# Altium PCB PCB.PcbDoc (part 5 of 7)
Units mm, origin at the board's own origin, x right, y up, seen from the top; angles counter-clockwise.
Board outline 243.2 x 142.8 mm, 4 copper layers (Top Layer, Layer 1, Layer 2, Bottom Layer), stack 0.603 mm thick; 451 components, 380 nets, 2276 pads, 1520 vias.
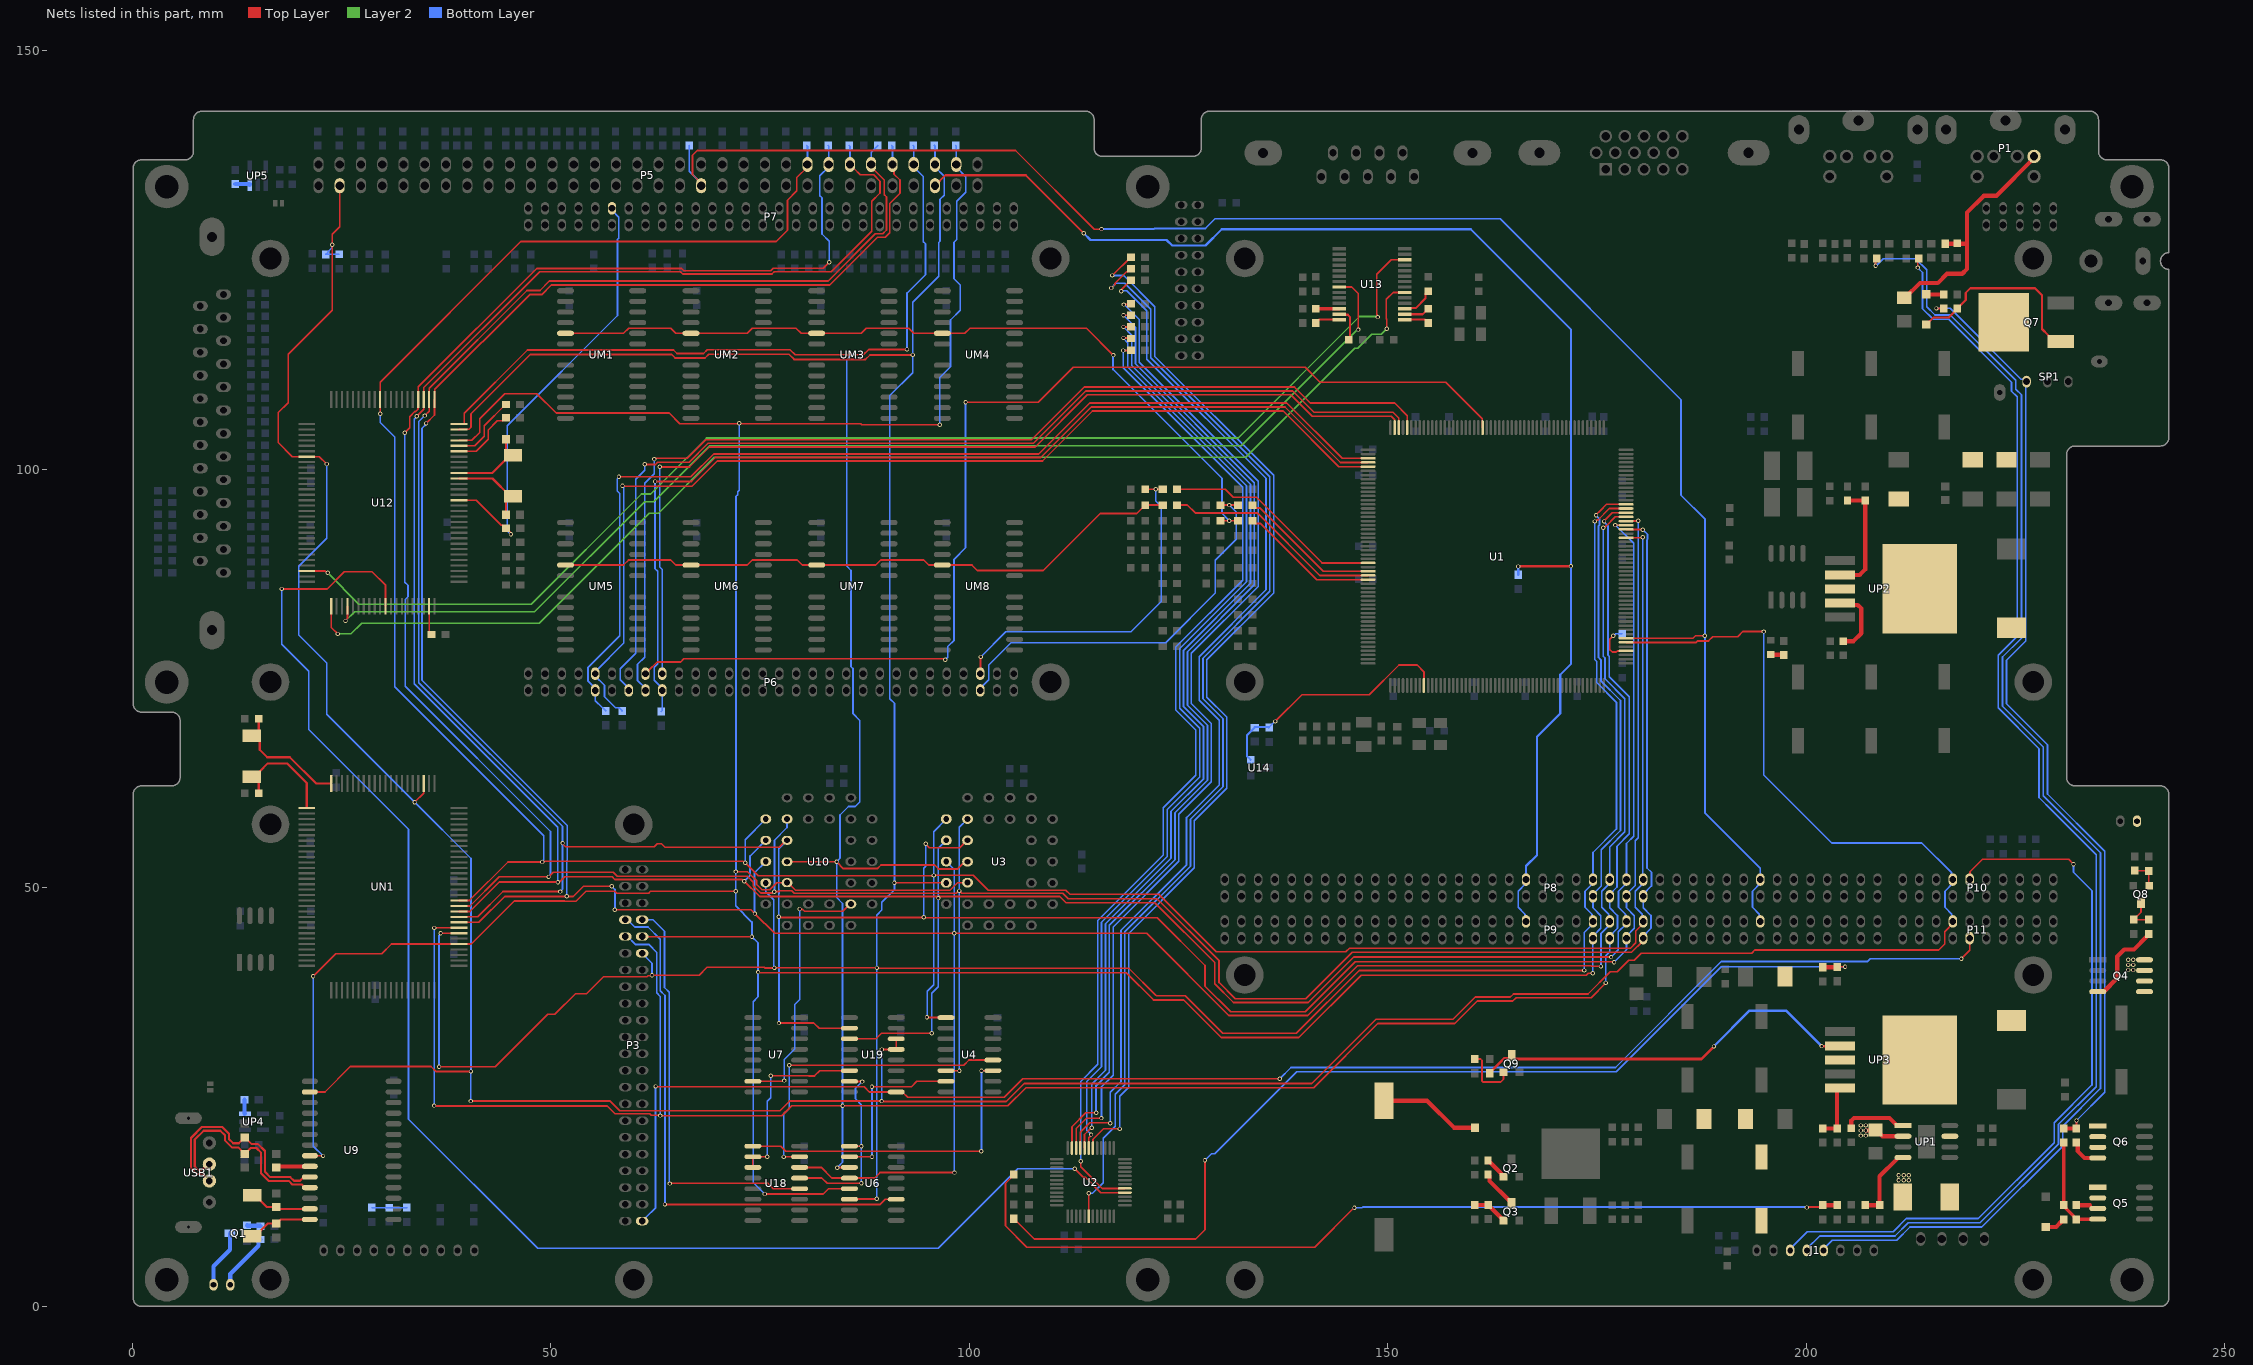
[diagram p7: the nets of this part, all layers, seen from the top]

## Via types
v1: diameter 0.508, hole 0.305, Top Layer to Bottom Layer, tented both sides, 1451 vias
v2: diameter 0.508, hole 0.3, Top Layer to Bottom Layer, 67 vias
v3: diameter 1.2, hole 1.2, Top Layer to Bottom Layer, 2 vias

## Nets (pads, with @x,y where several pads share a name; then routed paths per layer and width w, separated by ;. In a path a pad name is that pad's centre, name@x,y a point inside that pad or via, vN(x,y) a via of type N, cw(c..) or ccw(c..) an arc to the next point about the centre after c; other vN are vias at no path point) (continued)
NERROR#: P6.9 R83.1 U1.55 | length 126.6
  Top Layer w0.203: v1(58.126,99.126) 66.724,99.126 69.447,101.849 108.301,101.849 114.4,107.948 137.93,107.948 144.542,101.336 U1.55@147.647,101.336
  Bottom Layer w0.203: R83.1@56.552,71.136 56.552,71.174 56.209,71.517 56.171,71.517 55.3,72.387 P6.9@55.3,73.6 55.3,73.85 54.443,74.707 54.443,76.368 58.228,80.153 58.228,97.12 57.923,97.425 57.923,98.855 58.126,99.058 v1(58.126,99.126)
NetBAT1_1: BAT1.1 D1.A | length 12.2
  Top Layer w0.508: BAT1.1@149.53,24.585 154.663,24.585 157.886,21.361 D1.A@160.401,21.361
NetC10_1: C10.1 U9.9 | length 4.1
  Top Layer w0.508: C10.1@17.2,16.583 17.333,16.716 21.176,16.716 U9.9@21.2,16.74
NetC11_2: C11.2 U9.13 X4.1 | length 7.6
  Top Layer w0.254: X4.1@14.3,13.3 14.65,13.3 16.084,11.866 C11.2@17.206,11.866 17.412,11.66 U9.13@21.2,11.66
NetC12_2: C12.2 U9.14 X4.2 | length 7.7
  Top Layer w0.254: X4.2@14.3,8.4 14.65,8.4 16.15,9.9 C12.2@17.2,9.9 17.238,9.9 17.728,10.39 U9.14@21.2,10.39
NetC13_1: C13.1 U9.10 USB1.D+ | length 26.4
  Top Layer w0.254: USB1.D+@9.2,15 8.386,15.814 7.733,15.814 6.996,16.551 6.996,20.132 8.317,21.453 10.705,21.453 11.543,20.615 11.543,19.996 12.044,19.495 12.714,19.495 C13.1@13.419,20.2 ; C13.1@13.4,20.2 C13.1@13.419,20.2 ; U9.10@21.2,15.47 20.466,15.47 20.023,15.027 19.301,15.027 18.87,15.459 16.457,15.459 15.835,16.08 15.835,18.569 14.983,19.421 14.217,19.421 13.438,20.2 C13.1@13.419,20.2
NetC14_1: C14.1 U9.11 USB1.D- | length 24.9
  Top Layer w0.254: USB1.D-@9.2,17 8.995,17 8.266,16.272 7.922,16.272 7.453,16.74 7.453,19.943 8.506,20.996 10.515,20.996 11.086,20.426 11.086,19.806 11.88,19.012 12.647,19.012 C14.1@13.425,18.233 ; C14.1@13.406,18.233 C14.1@13.425,18.233 ; U9.11@21.2,14.2 20.598,14.2 20.228,14.57 19.112,14.57 18.68,15.002 16.267,15.002 15.378,15.891 15.378,18.38 14.819,18.939 14.15,18.939 13.444,18.233 C14.1@13.425,18.233
NetC17_1: C17.1 P1.4 R95.1 RP4.1 | length 29.2
  Top Layer w0.508: RP4.1@211.695,120.513 211.783,120.513 213.561,122.291 215.708,122.291 216.8,123.383 218.629,123.383 219.188,123.942 219.188,127.016 ; R95.1@216.572,126.965 218.045,126.965 219.137,126.965 219.188,127.016 ; P1.4@227.2,137.4 227.2,137.2 222.7,132.7 221.2,132.7 219.188,130.688 219.188,127.016
NetC22_2: C22.2 UP2.4 | length 8.3
  Top Layer w0.508: UP2.4@204.024,84.064 204.283,83.805 206.138,83.805 206.564,83.378 206.564,80.432 205.622,79.49 C22.2@204.38,79.49
NetC117_2: C117.2 U12.21 X5.2 | length 9.6
  Top Layer w0.254: U12.21@39.026,99.579 43.009,99.579 44.504,101.074 44.504,101.094 X5.2@45.118,101.708 ; C117.2@44.649,103.6 44.649,102.34 45.273,101.717 X5.2@45.477,101.717 ; X5.2@45.477,101.708 X5.2@45.749,101.708
NetC118_2: C118.2 U12.20 X5.1 | length 9.8
  Top Layer w0.254: U12.20@39.026,98.929 43.016,98.929 45.127,96.817 X5.1@45.273,96.817 ; C118.2@44.649,94.605 44.649,96.194 X5.1@45.273,96.817 ; X5.1@45.477,96.817 X5.1@45.273,96.817
NetC123_2: C123.2 U13.13 | length 4.2
  Top Layer w0.254: U13.13@144.2,118.55 144.273,118.477 145.202,118.477 145.452,118.227 145.452,115.652 C123.2@145.3,115.5
NetC124_1: C124.1 U13.12 | length 2.8
  Top Layer w0.381: C124.1@141.4,119.2 U13.12@144.2,119.2
NetC124_2: C124.2 U13.14 | length 3
  Top Layer w0.254: C124.2@141.4,117.5 141.8,117.9 U13.14@144.2,117.9
NetC125_1: C125.1 U13.16 | length 3.1
  Top Layer w0.254: U13.16@152,118.55 154.15,118.55 C125.1@154.8,119.2
NetC125_2: C125.2 U13.15 | length 3
  Top Layer w0.254: U13.15@152,117.9 154.4,117.9 C125.2@154.8,117.5
NetC126_1: C126.1 U13.17 | length 4
  Top Layer w0.254: U13.17@152,119.2 152.073,119.273 153.33,119.273 154.477,120.42 154.477,120.977 C126.1@154.8,121.3
NetCN1_1: CN1.1 UN1.51 X6.2 | length 13.4
  Top Layer w0.254: X6.2@14.251,63.292 14.601,63.292 15.224,63.915 15.224,63.92 16.191,64.887 18.477,64.887 20.826,62.539 UN1.51@20.826,59.55 ; X6.2@14.477,63.292 15.1,62.669 CN1.1@15.1,61.3
NetCN2_1: CN2.1 UN1.50 X6.1 | length 14.7
  Top Layer w0.254: X6.1@14.251,68.192 14.594,68.192 15.1,68.698 CN2.1@15.1,70.2 ; X6.1@14.563,68.192 14.601,68.192 15.224,67.569 15.224,66.515 16.115,65.624 18.807,65.624 21.956,62.475 UN1.50@23.751,62.475
NetCN5_1: CN5.1 RN3.1 RN4.1 | length 4.2
  Bottom Layer w0.203: RN3.1@28.6,11.8 RN4.1@32.8,11.8
NetCP1_2: CP1.2 UP1.1 | length 7.6
  Top Layer w0.508: CP1.2@205.37,21.301 205.37,22.215 205.675,22.52 209.917,22.52 210.831,21.606 UP1.1@211.542,21.606
NetCP7_1: CP7.1 DP7.A LP2.1 UP3.0 UP3.3
NetCP7_2: CP7.2 DP8.A DP9.K
NetDP1_K: DP1.K R104.1 | length 2.5
  Top Layer w0.508: DP1.K@228.6,9.5 229.839,9.5 230.516,10.177 230.554,10.177 230.745,10.368 R104.1@230.745,10.406
NetDP2_A: DP2.A Q7.1 R105.2 | length 23.3
  Top Layer w0.254: DP2.A@214.336,117.313 215.2,118.176 217.04,118.176 218.045,119.182 R105.2@218.045,119.22 218.045,119.258 219.035,120.248 219.035,121.097 219.594,121.656 227.316,121.656 228.154,120.818 228.154,116.779 228.909,116.024 228.909,115.965 229.238,115.636 Q7.1@230.389,115.636
NetDP2_K: DP2.K R107.1 | length 2.1
  Top Layer w0.508: DP2.K@214.336,120.913 214.34,120.916 216.416,120.916 R107.1@216.419,120.92
NetDP3_A: DP3.A DP4.A Q7.3
NetDP6_K: DP6.K LP1.2 UP2.0 UP2.3
NetJ1_4: J1.4 R19.2 | length 159.9
  Top Layer w0.203: v1(208.266,124.349) 208.266,125.087 R19.2@208.393,125.214
  Bottom Layer w0.203: J1.4@202.063,6.696 202.063,6.896 203.082,7.915 210.795,7.915 212.37,9.49 220.955,9.49 230.618,19.153 230.618,21.529 235.139,26.051 235.139,54.194 229.729,59.604 228.306,61.026 228.306,66.85 223.43,71.727 223.43,77.587 225.69,79.848 225.69,108.922 225.019,109.594 225.019,110.642 217.205,118.456 215.36,118.456 214.387,119.428 214.387,123.841 213.041,125.187 209.18,125.187 208.342,124.349 v1(208.266,124.349)
NetJ1_5: J1.5 R20.2 | length 155
  Top Layer w0.203: v1(213.295,124.12) 213.295,125.087 R20.2@213.422,125.214
  Bottom Layer w0.203: J1.5@200.063,6.696 200.063,6.896 201.59,8.423 210.584,8.423 212.159,9.998 220.744,9.998 230.11,19.363 230.11,21.74 234.631,26.261 234.631,53.983 229.37,59.245 227.798,60.816 227.798,66.64 222.922,71.517 222.922,77.798 225.182,80.058 225.182,108.675 224.511,109.346 224.511,110.431 216.995,117.948 215.149,117.948 213.879,119.218 213.879,123.536 v1(213.295,124.12)
NetL1_1: L1.1 RP3.1 UP1.2 | length 4.8
  Top Layer w0.508: v1(207.097,21.021) 208.164,21.021 RP3.1@208.24,21.098 208.328,21.098 209.09,20.336 UP1.2@211.542,20.336
  other v1: 211.009,15.078 211.619,15.078 212.228,15.078 211.009,15.687 211.619,15.687 212.228,15.687 206.488,20.412 207.097,20.412 206.488,21.021 206.488,21.631 207.097,21.631
NetL1_2: L1.2 UP1.7
NetLED2_1: LED2.1 R92.2 | length 1.6
  Top Layer w0.508: LED2.1@195.744,77.892 195.781,77.855 197.281,77.855 R92.2@197.318,77.818
NetLS1_1: LS1.1 Q1.C | length 6.9
  Bottom Layer w0.508: LS1.1@9.7,2.6 9.7,4.802 11.668,6.77 Q1.C@11.668,8.735
NetLS1_2: LS1.2 R3.1 | length 6.9
  Bottom Layer w0.508: LS1.2@11.7,2.6 11.7,3.877 15.071,7.248 15.071,7.809 15.262,8 R3.1@15.3,8
NetPP2_2: PP2.2 Q4.5 Q4.6 Q4.7 Q4.8
  other v1: 238.441,40.198 239.051,40.198 238.441,40.808 239.051,40.808 238.441,41.418 239.051,41.418
NetQ1_B: Q1.B R4.2 | length 1.6
  Bottom Layer w0.508: Q1.B@13.7,9.7 13.75,9.65 15.25,9.65 R4.2@15.3,9.6
NetQ2_B: Q2.B R6.2 | length 2.7
  Top Layer w0.508: R6.2@161.962,17.464 161.962,17.425 162.152,17.235 162.19,17.235 163.6,15.825 163.6,15.713 Q2.B@163.803,15.51
NetQ3_B: Q3.B R5.1 R7.2 | length 4.2
  Top Layer w0.508: R5.1@160.387,12.106 160.399,12.118 162.001,12.118 R7.2@162.012,12.13 162.012,12.091 163.6,10.504 163.6,10.48 Q3.B@163.803,10.277
NetQ3_C: Q3.C R6.1 | length 4.7
  Top Layer w0.508: R6.1@161.962,15.764 162.152,15.573 162.152,14.989 164.451,12.69 164.565,12.69 164.768,12.487 Q3.C@164.768,12.309
NetQ4_4: Q4.4 R101.1 | length 10.5
  Top Layer w0.508: Q4.4@234.809,37.608 235.52,37.608 237.146,39.233 237.146,41.824 237.984,42.662 239.127,42.662 240.714,44.25 240.714,44.326 R101.1@240.905,44.516
NetQ5_1: Q5.1 Q5.2 Q5.3 Q6.1 Q6.2 Q6.3 RP6.1 | length 1.7
  Top Layer w0.508: RP6.1@232.218,12.106 233.844,12.106 233.869,12.081
NetQ5_4: Q5.4 R104.2 R106.1 RP6.2 | length 12.4
  Top Layer w0.381: R106.1@230.745,19.574 R104.2@230.745,12.106 230.999,11.852 230.999,11.725 231.964,10.76 231.964,10.66 RP6.2@232.218,10.406 232.23,10.418 234.797,10.418 Q5.4@234.809,10.43
NetQ6_4: Q6.4 R108.1 | length 3.8
  Top Layer w0.508: R108.1@232.218,19.574 232.408,19.383 232.408,18.57 233.234,17.745 Q6.4@234.809,17.745
NetQ8_B: Q8.B R102.2 R103.1 | length 3.5
  Top Layer w0.203: R102.2@239.228,52.062 240.878,52.062 R103.1@240.905,52.035 240.905,50.295 Q8.B@240.943,50.257
NetQ8_C: Q8.C R100.2 R101.2 | length 4.1
  Top Layer w0.203: Q8.C@239.978,48.225 239.978,47.105 239.127,46.254 R100.2@239.127,46.216 R101.2@240.905,46.216
NetQ9_B: Q9.B R119.2 | length 7
  Top Layer w0.203: R119.2@160.376,29.564 161.063,29.564 161.239,29.388 161.239,26.941 161.358,26.822 163.5,26.822 163.817,27.14 Q9.B@163.817,27.965
NetQ9_C: Q9.C R118.1 UP3.2 | length 47.2
  Top Layer w0.203: R118.1@162.154,27.864 R118.1@162.154,27.902 ; Q9.C@164.452,29.667 Q9.C@164.782,29.997
  Top Layer w0.305: R118.1@162.154,27.902 163.919,29.667 Q9.C@164.452,29.667 ; Q9.C@164.782,29.997 164.782,29.87 165.087,29.566 187.452,29.566 v2(188.951,31.064) ; v2(201.813,31.105) UP3.2@204.024,31.105
  Bottom Layer w0.305: v2(188.951,31.064) 188.951,31.09 193.218,35.357 197.561,35.357 v2(201.813,31.105)
NetR8_2: R8.2 U2.43 | length 114
  Top Layer w0.203: U2.43@114.256,18.928 114.256,20.171 114.54,20.455 v1(114.54,20.537) ; v1(118.412,115.713) 119.213,115.713 R8.2@119.287,115.638
  Bottom Layer w0.203: v1(114.54,20.537) 114.021,21.057 114.021,26.873 115.792,28.644 115.792,45.914 123.63,53.753 123.63,59.372 127.515,63.257 127.515,69.073 125.127,71.46 125.127,78.603 133.114,86.59 133.114,98.054 118.931,112.237 118.931,115.119 118.412,115.638 v1(118.412,115.713)
NetR9_2: R9.2 U2.47 | length 118.6
  Top Layer w0.203: U2.47@112.256,18.928 112.256,21.476 113.919,23.139 v1(115.164,23.139) ; v1(118.412,118.413) R9.2@119.287,118.413
  Bottom Layer w0.203: v1(115.164,23.139) 115.138,23.165 115.138,26.391 116.72,27.972 116.72,45.53 124.558,53.368 124.558,58.988 128.443,62.873 128.443,69.457 126.055,71.845 126.055,78.219 134.042,86.205 134.042,98.41 119.839,112.613 119.839,116.986 v1(118.412,118.413)
NetR11_2: R11.2 U2.18 | length 135.1
  Top Layer w0.203: U2.18@114.256,10.778 114.265,10.787 114.265,13.504 v1(114.275,13.513) ; v1(116.951,121.682) 116.969,121.682 117.394,122.106 117.394,122.25 118.776,123.632 118.956,123.632 R11.2@119.299,123.974
  Bottom Layer w0.203: v1(114.275,13.513) 114.706,13.513 115.976,14.783 115.976,20.091 117.424,21.539 117.424,25.349 118.576,26.501 118.576,44.761 126.415,52.599 126.415,58.219 130.299,62.104 130.299,70.226 127.912,72.614 127.912,77.45 135.899,85.436 135.899,99.122 121.655,113.366 121.655,119.138 118.549,122.244 117.46,122.244 117.286,122.071 117.286,122.022 116.951,121.686 v1(116.951,121.682)
NetR12_2: R12.2 U2.29 | length 120.7
  Top Layer w0.203: v1(113.297,17.335) 113.297,16.672 115.866,14.103 U2.29@118.581,14.103 ; v1(118.372,114.214) 119.251,114.214 R12.2@119.299,114.262
  Bottom Layer w0.203: v1(113.297,17.335) 113.297,26.886 115.337,28.927 115.337,46.116 123.166,53.945 123.166,59.565 127.051,63.449 127.051,68.88 124.663,71.268 124.663,78.795 132.65,86.782 132.65,97.876 118.372,112.154 v1(118.372,114.214)
NetR13_2: R13.2 U2.44 | length 115.5
  Top Layer w0.203: U2.44@113.756,18.928 113.756,20.544 114.574,21.361 v1(114.605,21.361) ; v1(118.412,117.026) R13.2@119.287,117.026
  Bottom Layer w0.203: v1(114.605,21.361) 114.605,26.568 116.256,28.219 116.256,45.722 124.094,53.561 124.094,59.18 127.979,63.065 127.979,69.265 125.591,71.652 125.591,78.411 133.578,86.398 133.578,98.232 119.385,112.425 119.385,116.053 v1(118.412,117.026)
NetR14_2: R14.2 U2.46 | length 120.4
  Top Layer w0.203: U2.46@112.756,18.928 112.756,21.265 113.995,22.504 v1(115.773,22.504) ; v1(118.434,119.7) 119.187,119.7 R14.2@119.299,119.812
  Bottom Layer w0.203: v1(115.773,22.504) 115.773,26.213 117.184,27.624 117.184,45.338 125.022,53.176 125.022,58.796 128.907,62.68 128.907,69.649 126.52,72.037 126.52,78.026 134.506,86.013 134.506,98.588 120.293,112.801 120.293,117.92 118.512,119.7 v1(118.434,119.7)
NetR15_2: R15.2 U2.45 | length 124.4
  Top Layer w0.203: U2.45@113.256,18.928 113.256,20.803 114.399,21.946 v1@116.84,21.946 ; v1(118.136,121.299) 118.194,121.357 118.194,121.52 119.238,122.564 R15.2@119.276,122.564
  Bottom Layer w0.203: v1(116.84,21.895) 116.84,25.603 118.112,26.875 118.112,44.953 125.951,52.792 125.951,58.411 129.835,62.296 129.835,70.034 127.448,72.421 127.448,77.642 135.435,85.629 135.435,98.944 121.201,113.177 121.201,118.957 118.796,121.363 118.593,121.363 118.574,121.344 118.181,121.344 v1(118.136,121.299)
NetR16_2: R16.2 U2.42 | length 128.2
  Top Layer w0.203: U2.42@114.756,18.928 114.775,18.946 114.775,19.982 116.027,21.234 117.932,21.234 v1(117.958,21.209) ; v1@117.08,123.181 119.261,125.362 R16.2@119.299,125.362
  Bottom Layer w0.203: v1(117.08,123.18) 118.426,123.18 122.16,119.446 122.16,113.503 136.363,99.3 136.363,85.244 128.376,77.257 128.376,72.806 130.763,70.418 130.763,61.911 126.879,58.027 126.879,52.407 119.04,44.569 119.04,26.187 117.958,25.105 v1(117.958,21.209)
NetR88_2: R88.2 R89.1 R90.2 | length 121.4
  Top Layer w0.203: R90.2@105.321,10.476 105.321,10.438 105.664,10.095 105.702,10.095 107.745,8.052 127.025,8.052 128.143,9.169 v1(128.143,17.475) ; R89.1@203.662,40.554 203.697,40.589 v1(204.622,40.589)
  Top Layer w0.508: R88.2@201.967,40.527 201.98,40.54 203.648,40.54 R89.1@203.662,40.554
  Bottom Layer w0.203: v1(128.143,17.475) 128.93,18.263 129.311,18.263 139.09,28.042 177.292,28.042 189.84,40.589 v1(204.622,40.589)
NetR94_1: R94.1 U1.160 | length 5.1
  Top Layer w0.203: v1(176.922,80.127) 176.516,79.721 176.516,78.476 176.795,78.197 177.281,78.197 177.401,78.317 178.444,78.317 U1.160@178.463,78.336
  Bottom Layer w0.203: v1(176.922,80.127) 177.005,80.127 177.233,80.356 R94.1@177.989,80.356
NetR96_2: R96.2 R97.1 R99.2 | length 109.1
  Top Layer w0.203: R99.2@105.321,15.776 105.321,15.738 104.318,14.735 104.318,9.627 106.858,7.087 141.249,7.087 145.948,11.786 v1(145.999,11.786) ; v1(200.036,11.827) 200.095,11.885 201.746,11.885 R97.1@201.967,12.106
  Top Layer w0.508: R97.1@201.967,12.106 R96.2@203.662,12.106
  Bottom Layer w0.203: v1(145.999,11.786) 146.914,11.786 147.015,11.887 199.893,11.887 199.954,11.827 v1(200.036,11.827)
NetR106_2: R106.2 R107.2 R108.2 SP1.3 | length 112.7
  Top Layer w0.203: R108.2@232.218,21.274 232.269,21.324 v1(232.269,22.215)
  Top Layer w0.254: v1(215.53,119.243) 216.396,119.243 R107.2@216.419,119.22
  Top Layer w0.508: R106.2@230.745,21.274 R108.2@232.218,21.274
  Bottom Layer w0.203: v1(215.53,119.243) 217.18,119.243 225.644,110.779 226.021,110.779 SP1.3@226.3,110.5 ; SP1.3@226.211,109.981 226.211,79.505 223.912,77.206 223.912,72.025 228.814,67.122 228.814,61.23 235.647,54.397 235.647,25.593 v1(232.269,22.215)
NetR110_1: R110.1 R111.1 UP2.2 | length 13.6
  Top Layer w0.508: UP2.2@204.024,87.392 206.361,87.392 207.021,88.052 R110.1@207.021,96.282 R111.1@204.912,96.282
NetR112_2: R112.2 R113.2 UP1.4 | length 8.9
  Top Layer w0.508: R113.2@207.053,12.106 R112.2@208.748,12.106 208.748,15.56 210.812,17.624 210.812,17.749 210.859,17.796 UP1.4@211.542,17.796
NetR114_2: R114.2 R115.2 UP3.5 | length 6.7
  Top Layer w0.508: R114.2@201.967,21.274 R115.2@203.662,21.274 203.662,25.797 203.941,26.076 UP3.5@204.024,26.076
NetR116_2: R116.2 UP5.3 | length 1.8
  Bottom Layer w0.508: R116.2@12.3,134.1 14.011,134.1 14.032,134.079 UP5.3@14.032,134.017
NetR117_2: R117.2 UP4.3 | length 1.7
  Bottom Layer w0.508: R117.2@13.4,24.7 13.4,23.044 13.421,23.023 UP4.3@13.437,23.023
NetR145_1: R145.1 U12.26 | length 8.3
  Top Layer w0.203: U12.26@39.026,102.829 40.899,102.829 42.023,103.952 42.023,105.206 R145.1@44.577,107.76
NetR146_1: R146.1 U12.25 | length 7.9
  Top Layer w0.203: U12.25@39.026,102.179 41.062,102.179 42.505,103.622 42.505,104.714 43.608,105.817 44.272,105.817 R146.1@44.615,106.16
NetR147_1: R147.1 U12.99 | length 3.4
  Top Layer w0.203: U12.99@35.451,83.654 35.451,80.349 R147.1@35.5,80.3
NetU4_7: U4.7 U6.2 | length 20.3
  Top Layer w0.203: U6.2@85.671,17.882 v1(88.367,17.882) ; v1(88.352,26.254) 93.077,26.254 93.723,26.9 U4.7@97.212,26.9
  Bottom Layer w0.203: v1(88.352,26.254) 88.365,26.241 v1@88.365,17.805
NetU4_11: U4.11 U18.1 | length 38.5
  Top Layer w0.203: U18.1@74.128,19.153 77.469,19.153 78.08,18.542 v1(101.422,18.542) ; v1@101.448,28.169 U4.11@102.799,28.169
  Bottom Layer w0.203: v1(101.422,18.542) 101.435,18.555 101.435,28.156 v1(101.448,28.169)
NetU4_12: U4.12 U18.15 | length 37.7
  Top Layer w0.203: v1(77.822,17.872) 77.827,17.877 79.711,17.877 U18.15@79.716,17.883 ; v1(78.472,28.819) 99.325,28.819 99.946,29.44 U4.12@102.8,29.44
  Bottom Layer w0.203: v1(77.822,17.872) 77.822,23.009 78.472,23.659 v1(78.472,28.819)
NetU6_1: U6.1 U18.13 U19.7 | length 23.4
  Top Layer w0.203: U18.13@79.716,15.343 82.371,15.343 83.007,14.707 v1(87.097,14.707) ; U6.1@85.671,19.152 v1(87.097,19.152) ; U19.7@85.67,26.9 85.684,26.887 87.185,26.887 v1(87.198,26.873)
  Bottom Layer w0.203: v1(87.097,14.707) v1(87.097,19.152) 87.097,24.105 86.385,24.816 86.385,26.06 v1(87.198,26.873)
NetU7_7: U7.7 U10.22 | length 31.6
  Top Layer w0.203: U7.7@74.128,26.9 77.715,26.9 77.805,26.99 v1(77.888,26.99) ; v1(79.716,47.488) 79.775,47.43 80.098,47.43 80.294,47.234 84.883,47.234 85.721,48.072 U10.22@85.838,48.072
  Bottom Layer w0.203: v1(77.888,26.99) 77.888,29.515 79.131,30.758 79.131,36.083 79.716,36.668 v1(79.716,47.488)
NetU18_2: U18.2 U18.3 U19.6 | length 22.5
  Top Layer w0.203: U18.3@74.128,16.613 U18.2@74.128,17.883 v1(75.844,17.882) ; v1(76.276,27.559) 76.286,27.549 80.807,27.549 80.823,27.534 81.483,27.534 82.12,28.17 U19.6@85.67,28.17
  Bottom Layer w0.203: v1(75.844,17.882) 75.844,24.511 76.276,24.943 v1(76.276,27.559)
NM/IO#: P6.13 U1.50 | length 124.9
  Top Layer w0.203: v1@61.2,100.6 62.492,100.6 62.772,100.879 66.536,100.879 68.772,103.114 107.656,103.114 113.919,109.377 138.626,109.377 141.163,106.84 150.612,106.84 151.305,106.147 U1.50@151.305,104.994
  Bottom Layer w0.203: P6.13@59.3,73.6 59.3,73.85 58.279,74.871 58.279,76.19 60.133,78.044 60.133,98.847 61.2,99.914 v1(61.2,100.625)
NPEREQ: P6.10 R26.1 U1.57 | length 125.6
  Top Layer w0.203: v1(58.558,98.06) 58.616,98.002 66.862,98.002 69.867,101.006 108.731,101.006 114.703,106.978 137.485,106.978 144.127,100.336 U1.57@147.647,100.336
  Bottom Layer w0.203: R26.1@58.507,71.136 58.507,71.174 58.164,71.517 57.72,71.517 56.399,72.837 56.399,74.212 55.3,75.311 P6.10@55.3,75.6 55.3,75.85 58.711,79.261 58.711,97.839 58.667,97.882 58.667,97.893 58.558,98.003 v1(58.558,98.06)
NREADY#: P6.16 U1.30 | length 135.5
  Top Layer w0.203: P6.16@61.3,75.6 61.3,75.634 61.668,76.002 61.702,76.002 62.703,77.003 65.518,77.003 65.883,77.368 96.904,77.368 97.022,77.251 v1(97.104,77.251) ; v1(99.543,108.026) 108.225,108.026 112.406,112.207 140.118,112.207 141.896,110.429 156.914,110.429 161.286,106.057 161.286,105.012 U1.30@161.305,104.994
  Bottom Layer w0.203: v1(97.104,77.251) 97.409,77.556 97.409,78.842 98.171,79.604 98.171,89.281 99.543,90.653 v1(99.543,108.026)
NREADYO#: P6.17 R84.1 U1.56 | length 119.9
  Top Layer w0.203: v1(62.452,98.56) 62.459,98.568 66.801,98.568 69.661,101.428 108.516,101.428 114.551,107.463 137.707,107.463 144.335,100.836 U1.56@147.647,100.836
  Bottom Layer w0.203: v1(62.452,98.56) 62.444,98.553 62.444,88.154 62.775,87.823 62.775,76.8 62.343,76.368 62.343,74.807 63.3,73.85 P6.17@63.3,73.6 63.3,71.204 R84.1@63.181,71.085
NW/R#: P6.15 U1.48 | length 125.2
  Top Layer w0.203: v1@62.34,101.336 66.28,101.336 68.486,103.542 107.428,103.542 113.732,109.845 138.83,109.845 140.742,107.934 150.8,107.934 152.305,106.429 U1.48@152.305,104.994
  Bottom Layer w0.203: P6.15@61.3,73.6 61.3,73.85 60.336,74.814 60.336,76.698 61.2,77.562 61.2,98.339 62.34,99.479 v1(62.34,101.237)
OSC: P5.59 P8.43 P9.43 R93.2 | length 166.2
  Top Layer w0.254: P5.59@95.89,133.9 97.134,135.144 106.742,135.144 v1(113.651,128.235) ; v1(165.568,88.408) 165.594,88.433 171.842,88.433 v1(171.868,88.458)
  Bottom Layer w0.203: P9.43@166.384,46.116 166.384,46.865 165.558,47.691 165.558,49.622 P8.43@166.5,50.564
  Bottom Layer w0.254: v1(113.651,128.235) 114.464,127.422 123.557,127.422 124.217,126.762 128.205,126.762 130.135,128.692 159.904,128.692 171.893,116.703 171.893,88.484 v1(171.868,88.458) 171.893,88.433 171.893,76.774 170.585,75.466 170.585,70.844 167.829,68.088 167.829,53.945 166.5,52.616 P8.43@166.5,51 ; R93.2@165.568,87.417 v1(165.568,88.408)
OSD: J1.6 P10.11 | length 87.2
  Top Layer w0.203: P10.11@219.5,51 219.546,51.046 219.546,51.936 221.042,53.432 231.329,53.432 v1(231.913,52.848)
  Bottom Layer w0.203: J1.6@198.063,6.696 198.063,6.896 200.098,8.931 210.374,8.931 211.949,10.506 220.534,10.506 229.602,19.574 229.602,21.95 234.123,26.471 234.123,49.671 231.913,51.881 v1(231.913,52.848)
PIDECS1#: P3.37 U18.12 | length 49.4
  Top Layer w0.203: v1(64.186,14.681) 64.211,14.707 75.946,14.707 76.58,14.073 U18.12@79.716,14.073
  Bottom Layer w0.203: P3.37@60.9,46.2 62.207,46.2 63.576,44.831 63.576,38.1 64.127,37.549 64.127,14.74 v1(64.186,14.681)
PIDECS3#: P3.38 U6.11 | length 64.9
  Top Layer w0.203: v1(63.627,12.192) 89.332,12.192 89.943,12.803 U6.11@91.258,12.803
  Bottom Layer w0.203: P3.38@58.9,46.2 59.15,46.2 60.011,45.339 61.595,45.339 63.068,43.866 63.068,37.719 63.627,37.16 v1(63.627,12.192)
PWG: C1.2 R1.2 U1.113 U14.2 | length 29.8
  Top Layer w0.203: v1(136.55,69.901) 139.741,73.091 147.763,73.091 151.319,76.647 153.503,76.647 154.305,75.846 U1.113@154.305,74.206
  Bottom Layer w0.203: R1.2@135.799,69.149 135.799,69.187 136.512,69.901 v1(136.55,69.901)
  Bottom Layer w0.254: U14.2@133.604,65.303 133.172,65.735 133.172,68.261 134.061,69.149 C1.2@134.099,69.149 ; C1.2@134.099,69.249 135.699,69.249 R1.2@135.799,69.149
RAS0#: CM1.1 RM13.2 UM1.5 UM2.5 UM3.5 UM4.5 | length 96.2
  Top Layer w0.203: UM1.5@51.739,116.27 58.673,116.27 59.282,116.879 64.3,116.879 64.91,116.27 UM2.5@66.747,116.27 73.441,116.27 74.05,116.879 79.286,116.879 79.896,116.27 UM3.5@81.756,116.27 87.081,116.27 87.69,116.879 92.748,116.879 93.358,116.27 UM4.5@96.764,116.27 99.455,116.27 100.064,116.879 113.993,116.879 v1(117.207,113.665) ; CM1.1@130,93.877 RM13.2@132.1,93.875
  Bottom Layer w0.203: v1(117.207,113.665) 117.156,113.614 117.156,111.953 130.175,98.934 130.175,94.751 v2(131.049,93.877)
RAS1#: CM2.1 RM14.2 UM5.5 UM6.5 UM7.5 UM8.5 | length 76.4
  Top Layer w0.203: UM5.5@51.739,88.579 58.673,88.579 59.282,89.189 64.3,89.189 64.91,88.579 UM6.5@66.747,88.579 73.441,88.579 74.05,89.189 79.439,89.189 80.048,88.579 UM7.5@81.756,88.579 88.818,88.579 89.428,89.189 94.552,89.189 95.161,88.579 UM8.5@96.764,88.579 100.301,88.579 100.955,87.925 108.829,87.925 115.646,94.742 119.991,94.742 CM2.1@121,95.751 RM14.2@123.1,95.75
RAS2#: CM3.1 P6.55 RM15.2 | length 48.1
  Top Layer w0.203: CM3.1@130,95.752 v2(131.049,95.752) RM15.2@132.098,95.752
  Bottom Layer w0.203: P6.55@101.3,73.6 101.3,73.85 102.311,74.861 102.311,76.632 104.978,79.299 123.444,79.299 129.385,85.239 129.385,89.151 131.877,91.643 131.877,94.924 v2(131.049,95.752)
RAS3#: CM4.1 P6.56 RM16.2 | length 42.1
  Top Layer w0.203: P6.56@101.323,75.623 101.323,77.574 v2(101.346,77.597) ; CM4.1@121,97.627 RM16.2@123.098,97.627
  Bottom Layer w0.203: v2(101.346,77.597) 104.343,80.594 119.304,80.594 122.936,84.226 122.936,95.555 122.25,96.241 v2(122.25,97.638)
RASJ0: RM13.1 U1.84 | length 16.8
  Top Layer w0.203: RM13.1@133.8,93.875 134.143,93.532 134.79,93.532 141.486,86.836 U1.84@147.647,86.836
RASJ1: RM14.1 U1.83 | length 26.3
  Top Layer w0.203: RM14.1@124.8,95.75 126.044,95.75 126.986,94.808 134.403,94.808 141.875,87.336 U1.83@147.647,87.336
RASJ2: RM15.1 U1.82 | length 17.1
  Top Layer w0.203: RM15.1@133.8,95.75 134.143,95.407 134.693,95.407 142.264,87.836 U1.82@147.647,87.836
RASJ3: RM16.1 U1.80 | length 26.5
  Top Layer w0.203: RM16.1@124.8,97.625 130.57,97.625 131.532,96.663 134.301,96.663 142.128,88.836 U1.80@147.647,88.836
RD#: P7.12 R139.1 U12.16 | length 52.9
  Top Layer w0.203: U12.16@39.026,96.329 41.088,96.329 44.079,93.338 44.26,93.338 44.498,93.1 R139.1@44.498,92.995 ; R139.1@44.641,92.995 44.679,92.995 45.165,92.509 45.165,92.327 v1(45.223,92.268)
  Bottom Layer w0.203: v1(45.223,92.268) 44.802,92.69 44.802,105.24 57.954,118.392 57.954,127.478 58.105,127.629 58.105,130.145 57.3,130.95 P7.12@57.3,131.2
REFSH#: P5.37 P8.15 P9.15 R28.1 U1.163 | length 217.1
  Top Layer w0.203: P5.37@67.95,133.9 67.95,134.2 66.915,135.235 66.915,137.531 67.493,138.11 105.503,138.11 114.921,128.692 115.759,128.692 v1(115.784,128.717) ; U1.163@178.463,79.836 186.461,79.836 186.752,80.127 v1(187.87,80.127)
  Bottom Layer w0.203: R28.1@66.519,138.7 66.519,135.631 67.95,134.2 P5.37@67.95,133.9 ; v1(115.784,128.717) 122.027,128.717 122.095,128.786 128.197,128.786 129.348,129.937 139.546,129.937 163.43,129.937 185.025,108.342 185.025,96.915 187.895,94.045 187.895,80.127 187.895,58.943 194.5,52.338 P8.15@194.5,51 ; P9.15@194.384,46.116 194.384,46.865 193.558,47.691 193.558,49.622 P8.15@194.5,50.564
RESET#: P3.1 P11.12 U19.9 | length 183
  Top Layer w0.203: v1(62.509,26.289) 62.56,26.238 87.427,26.238 88.035,25.63 U19.9@91.258,25.63 91.995,25.63 92.631,24.994 104.165,24.994 106.375,27.203 v1(137.081,27.203) ; v2(218.516,41.554) 219.5,42.538 P11.12@219.5,44
  Bottom Layer w0.203: P3.1@60.9,10.2 60.934,10.2 61.302,10.568 61.302,10.602 62.509,11.809 v1(62.509,26.289) ; v1(137.081,27.203) 137.084,27.203 138.43,28.55 177.19,28.55 189.865,41.224 207.315,41.224 207.645,41.554 v2(218.516,41.554)
RI1#: U12.84 U13.8 | length 144.2
  Top Layer w0.203: v1(25.462,81.905) 25.462,81.988 25.701,82.226 U12.84@25.701,83.654 ; U13.8@144.2,121.8 145.663,121.8 146.442,121.021 146.442,116.754 v1(146.484,116.712)
  Layer 2 w0.203: v1(25.462,81.905) 26.553,82.996 48.039,82.996 61.198,96.155 62.29,96.155 68.97,102.835 132.463,102.835 146.22,116.592 146.281,116.592 146.401,116.712 v1(146.484,116.712)
RSTDRV: C9.1 P5.3 P10.13 P11.13 R61.1 U1.162 U9.2 U12.57 U19.13 U19.14 UN1.33 | length 417.7
  Top Layer w0.203: U9.2@21.2,25.63 23.009,25.63 26.046,28.667 35.673,28.667 36.257,28.083 v1(40.448,28.083) ; v1(23.227,100.65) 23.201,100.65 22.323,101.529 U12.57@20.826,101.529 19.105,101.529 17.41,103.223 17.41,106.797 18.604,107.991 18.604,113.757 23.887,119.04 v1(23.887,126.838) 23.878,126.847 23.878,128.098 24.77,128.991 P5.3@24.77,133.9 ; v1(33.711,60.233) 34.799,61.321 UN1.33@34.801,62.475 UN1.33@34.801,62.475 ; v1(40.411,24.536) 57.074,24.536 58.215,23.395 77.37,23.395 78.511,24.536 v1(89.51,24.536) ; v1@89.51,24.486 104.387,24.486 106.546,26.645 140.912,26.645 148.583,34.315 157.785,34.315 160.442,36.973 164.633,36.973 164.998,37.338 173.909,37.338 176.567,39.995 177.405,39.995 178.776,41.367 179.442,41.367 180.28,42.205 193.458,42.205 193.839,42.586 215.81,42.586 216.521,43.297 216.521,44.771 217.5,45.75 P11.13@217.5,46 ; v1(89.521,30.699) 89.526,30.704 91.253,30.704 U19.13@91.258,30.71 U19.14@91.258,31.98 ; U1.162@178.463,79.336 186.85,79.336 187.031,79.518 188.301,79.518 188.809,80.026 191.781,80.026 192.391,80.635 v1(194.905,80.635)
  Bottom Layer w0.203: v1(23.227,100.65) 23.227,92.218 23.227,91.786 19.874,88.433 19.874,80.229 23.227,76.876 23.227,70.738 33.721,60.243 40.451,53.513 40.451,29.937 40.448,29.934 v1(40.448,28.083) 40.43,28.064 40.43,24.555 v1(40.411,24.536) ; v1(23.887,126.838) 23.829,126.779 23.829,126.467 23.365,126.003 23.365,125.965 R61.1@23.1,125.7 C9.1@24.7,125.7 ; v1(89.51,24.536) 89.515,24.542 89.515,30.693 v1(89.521,30.699) ; v1@194.915,80.635 194.915,63.494 203.03,55.379 213.774,55.379 217.348,51.805 217.348,51.152 P10.13@217.5,51 ; P11.13@217.384,46.116 217.384,46.865 216.558,47.691 216.558,49.622 P10.13@217.5,50.564
RSTNP: P6.18 U1.51 | length 118.4
  Top Layer w0.203: v1@63.003,100.295 66.559,100.295 68.956,102.693 107.871,102.693 114.096,108.918 138.378,108.918 140.956,106.34 150.405,106.34 150.805,105.94 U1.51@150.805,104.994
  Bottom Layer w0.203: v1(63.003,100.32) 63.003,98.799 63.01,98.792 63.01,94.514 63.003,94.506 63.003,88.347 63.3,88.05 P6.18@63.3,75.6
RTS1#: U12.81 U13.20 | length 150.1
  Top Layer w0.203: U12.81@23.751,83.654 23.751,81.127 v1(24.522,80.356) ; v1(149.871,116.805) 149.871,117.956 149.82,118.007 149.82,120.335 150.635,121.15 U13.20@152,121.15
  Layer 2 w0.203: v1(24.522,80.356) 26.12,80.356 27.389,81.624 48.607,81.624 61.766,94.783 62.858,94.783 69.538,101.463 133.031,101.463 146.036,114.468 146.391,114.468 148.068,116.144 149.211,116.144 v1(149.871,116.805)
RTS2#: U2.28 U12.91 | length 183.1
  Top Layer w0.203: v1(17.856,85.725) 23.266,85.725 25.324,87.782 28.626,87.782 30.251,86.158 U12.91@30.251,83.654 ; v1(112.595,16.456) 113.608,15.443 113.868,15.443 115.709,13.603 U2.28@118.581,13.603
  Bottom Layer w0.203: v1(17.856,85.725) 17.856,79.121 21.082,75.895 21.082,68.936 32.995,57.023 32.995,22.377 48.412,6.96 96.266,6.96 105.763,16.456 v1(112.595,16.456)
RXD1: U12.78 U13.26 | length 153.1
  Top Layer w0.203: U12.78@20.826,87.879 23.013,87.879 23.246,87.646 v1(23.328,87.646) ; v1(148.779,118.202) 148.721,118.26 148.721,118.511 148.677,118.555 148.677,123.333 150.395,125.05 U13.26@152,125.05
  Layer 2 w0.203: v1(23.328,87.646) 27.064,83.91 47.66,83.91 60.819,97.069 61.911,97.069 68.591,103.749 132.084,103.749 146.613,118.278 148.508,118.278 148.525,118.26 148.721,118.26 v1(148.779,118.202)
SA0: P3.35 P5.62 P8.36 P9.36 R63.1 U1.195 U3.12 U6.5 U9.8 U10.12 U12.27 UN1.5 | length 492.1
  Top Layer w0.203: U9.8@21.2,18.01 21.213,17.997 22.77,17.997 v1(22.784,17.983) ; v1(21.59,39.446) 24.282,42.139 29.794,42.139 30.956,43.3 UN1.5@39.026,43.3 40.481,43.3 45.618,48.438 51.662,48.438 51.672,48.428 53,48.428 54.191,49.619 57.624,49.619 57.857,49.386 61.679,49.386 61.9,49.606 v1(72.071,49.606) ; U12.27@39.026,103.479 40.559,103.479 41.489,104.41 41.489,106.061 44.487,109.058 48.322,109.058 50.633,106.746 64.146,106.746 65.416,105.476 87.032,105.476 87.16,105.348 v1(96.455,105.348) ; P3.35@60.9,44.2 60.915,44.185 74.001,44.185 v1(74.016,44.171) ; v1(72.071,51.954) 72.08,51.945 73.486,51.945 74.575,50.855 74.575,50.413 75.214,49.774 76.142,49.774 77,50.632 U10.12@78.218,50.632 78.335,50.632 79.231,49.736 97.684,49.736 98.58,50.632 U3.12@99.783,50.632 ; 75.024,39.887 118.737,39.887 122.007,36.617 125.614,36.617 130.1,32.131 139.342,32.131 146.799,39.589 173.705,39.589 173.925,39.809 174.476,39.809 v1(174.484,39.817) ; v1(75.54,13.437) 82.523,13.437 83.16,14.073 U6.5@85.67,14.073 ; v1(174.866,94.528) 174.866,94.579 175.432,95.145 176.123,95.836 U1.195@178.463,95.836
  Bottom Layer w0.203: v1(21.59,39.446) 21.615,39.421 21.615,19.152 v1(22.784,17.983) ; v1(72.503,105.525) 72.503,97.526 72.325,97.348 72.325,96.996 72.114,96.785 72.114,51.997 v1(72.071,51.954) v1(72.071,49.606) 72.071,47.868 74.016,45.923 v1(74.016,44.171) 74.752,43.434 74.752,37.008 74.168,36.424 74.168,14.808 v1(75.54,13.437) ; v1(96.455,105.348) 96.455,110.988 97.739,112.272 97.739,117.856 98.908,119.024 98.908,122.037 98.157,122.788 98.157,127.143 98.495,127.481 98.495,132.028 99.579,133.112 99.579,134.991 98.43,136.14 P5.62@98.43,136.44 98.43,138.63 R63.1@98.36,138.7 ; v1(174.484,39.817) 174.492,39.826 174.492,43.992 P9.36@174.5,44 ; P9.36@174.5,44.25 175.437,45.187 175.437,46.701 174.5,47.638 P8.36@174.5,49 174.5,49.25 175.485,50.235 175.485,54.56 177.784,56.859 177.784,72.402 175.449,74.737 175.449,77.265 175.17,77.544 175.17,93.259 175.271,93.361 175.271,94.123 v1(174.866,94.528)
  other v1: 74.752,39.954
SA1: P3.33 P5.60 P8.35 P9.35 R64.1 U1.194 U3.11 U6.6 U10.11 U12.29 UN1.7 | length 440.2
  Top Layer w0.203: v1(36.638,28.641) 43.348,28.641 49.606,34.9 50.47,34.9 52.934,37.363 54.254,37.363 56.277,39.386 61.474,39.386 61.593,39.505 62.019,39.505 v1(62.078,39.564) 67.707,39.564 68.656,40.513 75.509,40.513 75.576,40.446 v1(76.704,40.446) ; v1(36.816,44.593) 36.819,44.596 39.022,44.596 UN1.7@39.026,44.6 ; U12.29@39.026,104.779 39.054,104.807 40.211,104.807 40.448,105.045 40.448,106.645 47.535,113.731 64.433,113.731 64.84,113.325 68.413,113.325 68.845,113.757 78.445,113.757 79.055,113.147 87.59,113.147 88.124,113.681 v1(93.229,113.681) ; v1@76.704,40.361 76.787,40.361 76.904,40.478 88.918,40.478 v1(88.949,40.446) ; U6.6@85.67,12.803 85.703,12.836 88.904,12.836 v1(88.937,12.868) ; v1@88.949,40.402 119.061,40.402 ; v1(91.045,50.638) 91.07,50.612 U3.11@97.242,50.612 ; 119.061,40.376 122.261,37.176 ; 122.314,37.124 125.793,37.124 130.278,32.639 139.065,32.639 146.574,40.148 v1(173.468,40.148) ; v1(174.712,93.792) 174.795,93.792 174.971,93.969 175.098,93.969 176.465,95.336 U1.194@178.463,95.336
  Bottom Layer w0.203: v1(36.638,28.641) 36.638,44.332 36.816,44.51 v1(36.816,44.593) ; P3.33@60.9,42.2 60.934,42.2 61.302,41.832 61.302,41.798 62.078,41.022 v1(62.078,39.564) ; U10.11@75.678,50.612 75.678,49.544 76.633,48.589 76.633,40.717 76.646,40.704 76.646,40.504 v1(76.704,40.446) ; v1(88.937,12.868) 88.943,12.874 88.943,40.44 v1(88.949,40.446) ; v1@88.937,40.446 88.937,46.752 89.546,47.361 89.546,48.276 91.045,49.774 v1(91.045,50.638) 91.045,72.053 90.495,72.602 90.495,108.838 93.229,111.572 v1(93.229,113.681) 93.229,119.98 96.353,123.104 96.353,127.117 96.495,127.259 96.495,132.288 96.988,132.781 96.988,135.042 95.89,136.14 P5.60@95.89,136.44 95.89,138.63 R64.1@95.82,138.7 ; v1(173.468,40.148) 173.468,44.679 174.5,45.711 P9.35@174.5,46 ; P9.35@174.384,46.116 174.384,46.865 173.558,47.691 173.558,49.622 P8.35@174.5,50.564 ; P8.35@174.5,51 174.5,54.235 177.303,57.039 177.303,72.202 174.954,74.552 174.954,77.06 174.712,77.301 v1(174.712,93.792)
SA2: P3.36 P5.58 P8.34 P9.34 R65.1 U1.193 U3.10 U6.3 U10.10 U12.30 UN1.8 | length 465.6
  Top Layer w0.203: v1(36.043,24.003) 36.093,23.952 56.718,23.952 57.656,23.014 61.822,23.014 61.976,22.86 v1@63.068,22.86 ; v1(36.054,45.228) 36.065,45.239 39.014,45.239 UN1.8@39.026,45.25 ; U12.30@39.026,105.429 39.607,105.429 39.635,105.457 39.635,106.696 47.204,114.265 64.654,114.265 65.061,113.858 68.236,113.858 68.693,114.316 78.572,114.316 79.182,113.706 v1(86.008,113.706) ; v1(63.068,22.809) 63.094,22.784 77.572,22.784 78.765,23.978 v1(84.847,23.978) 104.597,23.978 106.756,26.137 141.122,26.137 148.793,33.807 157.984,33.807 160.676,36.5 164.922,36.5 165.319,36.896 174.281,36.896 v1(176.033,38.649) ; U10.10@78.218,53.132 78.221,53.13 84.133,53.13 v1(84.136,53.127) 84.949,52.314 89.007,52.314 89.439,52.746 95.845,52.746 96.315,52.276 98.607,52.276 99.463,53.132 U3.10@99.783,53.132 ; v1(84.201,16.586) 84.214,16.6 85.657,16.6 U6.3@85.67,16.613 ; v1@86.037,113.706 87.336,113.706 87.971,114.341 v1(92.543,114.341) ; v1(175.83,93.792) 175.83,93.869 176.797,94.836 U1.193@178.463,94.836
  Bottom Layer w0.203: v1(36.043,24.003) 36.048,24.009 36.048,45.222 v1(36.054,45.228) ; P3.36@58.9,44.2 59.15,44.2 60.094,43.256 61.671,43.256 62.636,42.291 62.636,37.465 63.068,37.033 v1(63.068,22.809) ; v1(84.201,16.586) 84.847,17.232 v1(84.847,23.978) 84.847,48.149 84.136,48.86 v1(84.136,53.127) 84.542,53.533 84.542,58.715 85.558,59.731 86.371,59.731 86.905,60.264 86.905,70.006 86.105,70.805 86.105,76.183 85.863,76.425 85.863,87.925 85.33,88.458 85.33,92.052 85.355,92.078 85.355,113.082 85.979,113.706 v1(86.008,113.706) ; v1(92.543,114.341) 92.543,121.072 94.753,123.282 94.753,126.965 94.495,127.223 94.495,134.995 93.35,136.14 P5.58@93.35,136.44 93.35,138.63 R65.1@93.28,138.7 ; v1(175.83,93.792) 175.83,93.716 176.287,93.259 176.287,77.828 176.44,77.675 176.44,75.244 178.843,72.84 178.843,56.47 177.364,54.991 177.364,50.114 176.5,49.25 P8.34@176.5,49 176.5,47.638 177.437,46.701 177.437,45.187 P9.34@176.5,44.25 ; v1(176.033,38.649) 176.033,41.903 176.5,42.37 P9.34@176.5,44
SA3: P5.56 P8.33 P9.33 R66.1 U1.192 U3.9 U6.4 U10.9 U12.31 U18.14 UN1.9 | length 412.1
  Top Layer w0.203: v1(35.089,105.502) 36.101,106.514 U12.31@36.101,108.354 36.129,108.382 36.129,109.565 47.458,120.894 48.906,120.894 50.049,122.037 83.323,122.037 89.013,127.727 89.962,127.727 90.495,128.26 90.495,131.783 91.715,133.003 91.715,134.575 91.001,135.289 91.001,136.249 P5.56@90.81,136.44 ; UN1.9@39.026,45.9 41.4,45.9 44.487,48.987 v1@51.88,48.987 ; v1@51.903,48.987 52.67,48.987 53.899,50.216 v1(57.277,50.216) ; v1(57.633,47.396) 58.315,47.396 58.317,47.395 66.115,47.395 66.116,47.396 73.914,47.396 v1(74.371,46.939) 76.733,44.578 v1(98.197,44.578) 121.184,44.578 130.999,34.763 140.421,34.763 146.365,40.706 174.263,40.706 174.34,40.63 v1@175.398,40.63 ; U18.14@79.716,16.613 82.295,16.613 83.565,15.343 U6.4@85.67,15.343 88.673,15.343 89.332,16.002 v1(98.222,16.002) ; v1(175.728,93.028) 175.811,93.028 176.017,93.234 176.061,93.234 177.164,94.336 U1.192@178.463,94.336
  Bottom Layer w0.203: v1(35.089,105.502) 35.089,105.419 34.606,104.937 34.606,74.819 51.954,57.47 51.954,53.307 51.891,53.244 v1(51.891,48.999) ; v1(57.277,50.216) 57.277,50.188 57.658,49.807 57.658,47.422 v1(57.633,47.396) ; v1(74.371,46.939) 74.332,46.979 74.332,51.806 U10.9@75.678,53.152 ; R66.1@90.74,138.7 90.81,138.63 P5.56@90.81,136.44 ; U3.9@97.242,53.152 98.197,52.198 v1(98.197,44.578) v1@98.197,16.002 ; v1(175.449,40.63) 175.449,44.542 176.5,45.593 P9.33@176.5,46 ; v1(175.728,93.028) 175.728,77.686 175.944,77.47 175.944,74.99 178.314,72.621 178.314,56.703 176.5,54.889 P8.33@176.5,51 ; P9.33@176.384,46.116 176.384,46.865 175.558,47.691 175.558,49.622 P8.33@176.5,50.564
SA4: P5.54 P8.32 P9.32 R67.1 U1.191 U3.8 U10.8 U12.32 U19.2 UN1.10 | length 392.7
  Top Layer w0.203: v1(34.936,106.442) 35.451,106.956 U12.32@35.451,108.354 35.454,108.358 35.454,109.703 47.141,121.389 48.69,121.389 49.821,122.52 83.145,122.52 88.771,128.145 89.633,128.145 90.105,128.617 90.105,132.553 89.826,132.832 89.826,134.584 88.27,136.14 P5.54@88.27,136.44 ; UN1.10@39.026,46.55 41.262,46.55 44.283,49.571 v1(51.116,49.571) v1@51.174,49.629 ; v1(51.395,55.362) 51.395,55.285 51.74,54.94 62.357,54.94 62.687,55.27 63.221,55.27 63.637,54.854 77.263,54.854 78.101,55.692 U10.8@78.218,55.692 ; v1(77.227,46.548) 77.286,46.49 77.481,46.49 77.499,46.472 94.525,46.472 v1(94.55,46.498) 94.608,46.439 94.816,46.439 94.821,46.434 122.452,46.434 128.154,40.732 128.154,38.268 131.228,35.195 140.122,35.195 146.116,41.189 v1@177.018,41.189 ; v1(77.241,33.858) 77.259,33.876 81.418,33.876 82.044,33.25 U19.2@85.67,33.25 ; v1(94.779,55.286) 94.779,55.261 95.223,54.816 98.828,54.816 99.704,55.692 U3.8@99.782,55.692 ; U1.191@178.463,93.836 178.479,93.852 179.903,93.852 v1(179.919,93.869)
  Bottom Layer w0.203: v1(34.936,106.442) 34.225,105.73 34.225,74.534 51.395,57.363 v1(51.395,55.362) 51.395,49.85 v1(51.116,49.571) ; v1(77.241,33.858) 77.263,33.88 77.263,46.513 v1(77.227,46.548) 77.227,49.279 77.256,49.309 77.256,49.772 77.227,49.801 77.227,54.702 U10.8@78.218,55.692 ; P5.54@88.27,136.44 88.27,137.885 89.047,138.662 R67.1@89.047,138.7 ; v1(94.55,46.498) 94.55,52.368 94.779,52.596 v1(94.779,55.286) ; v1(177.018,41.129) 178.5,42.611 P9.32@178.5,44 178.5,44.25 179.437,45.187 179.437,46.701 178.5,47.638 P8.32@178.5,49 178.5,49.25 179.549,50.299 179.549,55.626 179.902,55.98 179.902,93.851 v1(179.919,93.869)
SA5: P5.52 P8.31 P9.31 R68.1 U1.190 U3.7 U10.7 U12.33 U19.3 UN1.11 | length 385.8
  Top Layer w0.203: v1(33.971,106.365) 34.801,107.195 U12.33@34.801,108.354 34.801,109.786 48.652,123.637 65.47,123.637 65.749,123.358 76.423,123.358 76.702,123.637 83.501,123.637 88.327,128.463 88.327,132.045 89.318,133.035 89.318,134.432 88.555,135.194 86.976,135.194 86.221,135.949 86.19,135.949 85.73,136.41 P5.52@85.73,136.44 ; UN1.11@39.026,47.2 40.332,47.2 43.846,50.714 50.811,50.714 v1(50.837,50.689) ; v1@50.837,50.714 50.964,50.714 50.989,50.689 51.649,51.349 57.312,51.349 57.647,51.014 72.841,51.014 73.04,50.816 v1(73.112,50.816) 73.112,50.798 74.936,48.974 v1@96.303,48.974 ; U19.3@85.67,31.98 88.846,31.98 89.495,32.629 95.505,32.629 v1(95.515,32.639) ; v1(96.303,48.796) v1@96.303,48.974 ; v1(176.668,41.748) 145.913,41.748 140.478,36.312 131.558,36.312 129.297,38.573 129.297,41.087 122.16,48.225 111.543,48.225 110.793,48.974 v1@96.303,48.974 ; v1(177.176,93.361) 177.189,93.348 178.45,93.348 U1.190@178.463,93.336
  Bottom Layer w0.203: v1(33.971,106.365) 33.971,106.283 33.692,106.004 33.692,74.412 50.837,57.267 v1(50.837,50.689) ; v1(73.112,50.816) 73.798,51.501 73.798,53.813 U10.7@75.678,55.692 ; R68.1@85.66,138.7 85.73,138.63 P5.52@85.73,136.44 ; v1(95.515,32.639) 95.49,32.664 95.49,37.404 96.288,38.202 96.288,48.781 v1(96.303,48.796) ; v1@96.288,48.796 96.288,49.073 96.303,49.088 96.288,49.103 96.288,54.738 U3.7@97.242,55.692 ; v1(176.668,41.748) 177.537,42.617 177.537,44.748 178.5,45.711 P9.31@178.5,46 ; v1(177.176,93.361) 179.373,91.164 179.373,56.187 178.5,55.314 P8.31@178.5,51 ; P9.31@178.384,46.116 178.384,46.865 177.558,47.691 177.558,49.622 P8.31@178.5,50.564
SA6: P5.50 P8.30 P9.30 R69.1 U1.189 U3.6 U4.6 U10.6 U12.34 UN1.12 | length 386.2
  Top Layer w0.203: v1(32.549,104.384) 33.133,104.968 33.133,106.317 33.74,106.924 33.869,106.924 34.122,107.177 34.122,108.325 U12.34@34.151,108.354 34.151,109.872 48.297,124.018 65.628,124.018 65.907,123.739 76.265,123.739 76.57,124.044 82.546,124.044 v1(83.249,124.746) ; UN1.12@39.026,47.85 40.327,47.85 43.826,51.349 49.697,51.349 v1(49.722,51.325) ; v1@49.736,51.336 50.282,51.882 57.439,51.882 57.926,51.395 73.497,51.395 74.194,50.697 74.194,50.255 75.056,49.393 76.468,49.393 76.615,49.54 v1(76.698,49.54) ; v1@76.77,49.571 77.286,49.571 77.387,49.673 78.756,49.673 79.073,49.355 98.417,49.355 98.709,49.647 v1(98.792,49.647) 99.084,49.355 111.174,49.355 111.822,48.707 122.414,48.707 129.831,41.291 129.831,38.7 131.761,36.769 140.198,36.769 145.735,42.307 179.112,42.307 180.5,43.695 P9.30@180.5,44 ; P5.50@83.19,136.14 P5.50@83.19,136.44 ; U4.6@97.213,28.169 v1(98.806,28.169) ; U1.189@178.463,92.836 178.48,92.819 180.444,92.819 v1(180.461,92.802)
  Bottom Layer w0.203: v1(32.549,104.384) 32.549,86.533 32.93,86.152 32.93,84.801 32.599,84.471 32.599,74.107 49.962,56.745 49.962,51.645 49.722,51.405 v1(49.722,51.325) ; v1(76.698,49.54) 76.719,49.562 76.719,55.718 78.218,57.216 U10.6@78.218,58.232 ; R69.1@83.12,138.7 83.19,138.63 P5.50@83.19,136.44 83.19,136.14 82.129,135.079 82.129,132.705 82.383,132.451 82.383,128.133 83.249,127.268 v1(83.249,124.746) ; v1(98.806,28.169) 98.792,28.183 v1(98.792,49.647) 98.792,57.242 U3.6@99.782,58.232 ; v1(180.461,92.802) 181.02,92.243 181.02,91.663 180.961,91.605 180.961,91.078 180.961,52.39 181.494,51.857 181.494,50.244 180.5,49.25 P8.30@180.5,49 180.5,47.638 181.437,46.701 181.437,45.187 180.5,44.25 P9.30@180.5,44
SA7: P5.48 P8.29 P9.29 R70.1 U1.187 U3.5 U4.1 U10.5 U12.41 UN1.13 | length 364.4
  Top Layer w0.203: U12.41@29.601,108.354 29.601,110.428 46.417,127.244 76.922,127.244 78.269,128.59 78.269,132.172 79.386,133.289 79.386,134.876 80.65,136.14 P5.48@80.65,136.44 ; v1(29.602,106.67) U12.41@29.601,108.353 ; UN1.13@39.026,48.5 40.266,48.5 44.868,53.102 v1(48.961,53.102) 49.019,53.16 49.214,53.16 49.232,53.178 72.976,53.178 ; v1@73.265,53.024 73.265,52.972 74.761,51.476 v1@95.703,51.476 ; v1(94.931,34.544) 94.943,34.532 97.2,34.532 U4.1@97.212,34.52 ; v1@95.724,51.507 95.731,51.514 100.455,51.514 102.233,49.736 111.53,49.736 112.025,49.241 122.617,49.241 129.475,42.383 144.973,42.383 145.405,42.815 178.98,42.815 179.615,43.45 179.615,44.865 180.5,45.75 P9.29@180.5,46 ; U1.187@178.463,91.836 178.476,91.849 180.415,91.849 v1(180.461,91.895)
  Bottom Layer w0.203: v1(29.602,106.67) 29.602,105.603 31.329,103.876 31.329,74.057 49.135,56.251 49.135,53.358 48.961,53.184 v1(48.961,53.102) ; v1(73.213,53.024) 73.214,53.025 73.214,55.769 U10.5@75.678,58.232 ; R70.1@80.58,138.7 80.65,138.63 P5.48@80.65,136.44 ; v1(94.931,34.544) v1@94.956,34.519 ; v1@94.956,34.544 94.956,37.658 95.744,38.446 95.744,51.476 v1@95.718,51.501 ; v1(95.729,51.501) 95.729,56.719 U3.5@97.242,58.232 ; v1(180.461,91.895) 180.432,91.865 180.432,51.068 P8.29@180.5,51 ; P9.29@180.5,46 180.384,46.116 180.384,46.865 179.558,47.691 179.558,49.622 P8.29@180.5,50.564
